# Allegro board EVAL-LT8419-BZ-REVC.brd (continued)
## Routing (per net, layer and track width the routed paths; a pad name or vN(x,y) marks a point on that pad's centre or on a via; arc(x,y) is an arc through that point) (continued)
V5: length 267.7
  TOP w0.254: 120.85,38.59 U7.9 ; R7.1 v1(105.4,27.28) ; R456.1 v1(109.57,27.28)
  TOP w0.305: C700.1 122.66,38.14 121.74,38.14 121.28,38.59 120.85,38.59
  TOP w0.381: C43.2 28.72,21.87 28.7,21.89 JP1.2
  L6_SIG w0.381: 123.83,32.7 123.83,35.67 122.55,36.95 v3(122.21,36.95) ; 123.83,32.7 131.95,24.59 203.63,24.59 205,25.96 JP3.1 214.19,25.96 v1(214.91,26.68) 215.82,27.59 224.16,27.59 224.22,27.53 v1(224.66,27.53) ; 123.83,32.7 122.8,32.7 117.16,27.06 111.18,27.06 110.96,27.28 v1(109.57,27.28) 108.83,28.02 106.13,28.02 v1(105.4,27.28) 102.65,30.04 102.65,39.29 103.26,39.91 103.26,40.35 v1(104.01,41.09) 105.07,40.02 106.09,40.02 106.76,40.69 106.76,44.53 108.49,46.26 108.49,47.27 107.45,48.31 107.45,48.42 v1(107.13,48.74) ; JP1.2 30.41,18.55 v1(32.51,18.55)
  L7_SIG w0.381: v1(32.51,18.55) 97.39,18.55 105.4,26.56 v1(105.4,27.28)
  BOTTOM w0.305: R6.2 v1(214.91,26.68)
  BOTTOM w0.381: R5.1 225.42,27.22 225.12,27.53 v1(224.66,27.53) ; R13.2 212.9,18.18 210.74,20.34 210.74,22.47 JP3.1
_N1: length 3.5
  TOP w0.203: C9.2 122.4,33.09 120.9,34.59 U7.1
_N2: length 8.3
  TOP w0.203: U7.4 121.02,36.09 122.21,34.9 v3(122.21,34.65) 122.4,34.46 C5.2
  L7_SIG w0.203: v3(126.4,33.78) 123.08,33.78 v3(122.21,34.65)
_N5: length 5.7
  TOP w0.203: U7.49 110.55,31.75 109.39,30.59 107.12,30.59 106.77,30.24 R17.1
_N7: length 8
  TOP w0.203: C11.2 v3(122.21,35.83) 121.84,35.83 121.06,36.62 121.06,36.83 120.8,37.09 U7.6
  L7_SIG w0.203: v3(126.4,35.15) 125.72,35.83 v3(122.21,35.83)
_N9: length 7.4
  TOP w0.203: C196.1 126.45,43.36 125.86,43.36 125.31,42.81 122.62,42.81 120.9,41.09 U7.14
_N20: length 8.8
  TOP w0.203: 126.4,39.81 R1.1 126.4,41.31 ; U7.13 120.94,40.59 122.78,42.43 125.21,42.43 125.63,42.01 C189.1
_N24: length 8.2
  TOP w0.203: R29.2 103.65,30.24 103.98,30.57 105.24,30.57 105.93,31.26 C39.1 106.63,32.23 108.55,34.15 U7.48
_N30: length 122.8
  TOP w0.203: U7.42 C2.1
  L6_SIG w0.203: E1.1 22.08,62.11 74.72,62.11 78.98,57.86 78.98,46.06 83.28,41.76 100.08,41.76 101.02,40.82 v3(101.02,37.68)
_N31: length 9.3
  TOP w0.203: U7.3 120.86,35.59 121.1,35.35 v3(121.1,35.09)
  L7_SIG w0.203: v3(121.1,35.09) 121.33,35.31 125.58,35.31 127.68,33.21 127.68,33.07 v3(127.86,32.89)
_N45: length 8
  TOP w0.203: U7.7 v3(121.1,37.59)
  L7_SIG w0.203: v3(121.1,37.59) v3(128.1,37.59)
_N68: length 3.3
  TOP w0.203: U7.44 107.32,36.59 106.2,35.47 R20.1
_N69: length 129.9
  TOP w0.203: v3(105.71,41.09) U7.35
  L6_SIG w0.203: v3(105.71,41.09) 102.92,43.88 83.32,43.88 80.06,47.14 80.06,58.33 75.06,63.33 22.85,63.33 20.13,66.04 20.13,71.68 E9.1
_N73: length 151.5
  TOP w0.203: U7.51 v3(111.55,31.54)
  L6_SIG w0.203: JP3.2 215.67,23.96 218.04,26.33 225.13,26.33 225.78,26.98 225.78,31.19 221.62,35.35 132.67,35.35 131.84,36.19 128.34,36.19 127.03,37.49 121.82,37.49 114.38,30.06 110.3,30.06 109.82,30.54 109.82,31.15 110.28,31.62 111.47,31.62 v3(111.55,31.54)
  BOTTOM w0.203: JP3.2 JP3.3
_N75: length 3.6
  TOP w0.203: U7.53 112.55,31.26 111.04,29.75 R44.2
_N76: length 120.4
  TOP w0.203: R456.2 109.57,30.23 109.98,30.65 v3(111.17,30.65) 111.35,30.65 112.05,31.35 U7.52
  L6_SIG w0.203: v3(111.17,30.65) 113.32,30.65 120.81,38.13 121.57,38.13 121.72,37.98 122.44,37.98 122.68,38.22 128.45,38.22 129.96,36.71 219.21,36.71 E21.1
_N78: length 26.4
  TOP w0.203: U7.50 111.05,31.28 v3(111.17,31.16)
  L7_SIG w0.203: v3(111.17,31.16) 110.94,31.16 108.87,29.09 108.87,24.88 115.91,17.84 117.46,17.84 119.99,15.32 E3.1
_N79: length 5.1
  TOP w0.203: R15.2 R9.2 122.92,43.62 122.46,43.16 122.37,43.16 120.8,41.59 U7.15
_N81: length 132.4
  TOP w0.203: C12.1 122.58,39.45 122.35,39.45 122.08,39.18 v3(122.08,38.85) 121.65,38.85 121.4,39.09 U7.10
  L6_SIG w0.203: E2.1 221.87,81.33 202.7,62.17 145.13,62.17 137.8,54.84 131.7,54.84 122.08,45.22 v3(122.08,38.85)
_N86: length 225.7
  TOP w0.203: v3(122.97,41.97) C148.1 122.4,41.21 120.78,39.59 U7.11
  L6_SIG w0.203: S1.2 221.59,21.08 224.14,21.08 226.65,23.59 226.65,45.81 223,49.47 193.6,49.47 189.87,53.2 182.89,53.2 179.8,50.12 179.8,46.74 177.92,44.85 126.95,44.85 124.08,41.97 v3(122.97,41.97)
  L7_SIG w0.203: S1.2 219.16,23.5 219.16,48.01 224.36,53.21 224.36,94.08 E5.1
_N95: length 4.9
  BOTTOM w0.203: C197.1 R468.1 R464.2 P28.1
_N100: length 6.1
  BOTTOM w0.203: J6.4 4.44,20.67 4.44,18.48 5.56,17.37 R415.1
_N101: length 7.8
  BOTTOM w0.203: R416.1 3.99,22.21 J6.6
_N102: length 9.6
  BOTTOM w0.203: J6.7 8.83,24.86 8.83,17.01 R12.1
_N108: length 12.9
  L5_GND w0.203: J6.11 14.92,29.96 v2(16.26,31.3)
  BOTTOM w0.203: J6.11 9.25,29.96 9.95,30.66 R439.2 ; U8.6 v2(16.26,31.3)
_N109: length 15.5
  L5_GND w0.171: 7.92,28.96 7.55,28.96
  L5_GND w0.203: v1(12.69,27.96) 11.69,28.96 7.92,28.96 ; J6.10 6.73,28.96 7.55,28.96
  BOTTOM w0.203: R440.1 12.69,32.29 12.93,32.54 C169.1 U8.8 ; R440.1 R441.1 v1(12.69,27.96) ; R440.1 R439.1
_N111: length 13.7
  L5_GND w0.203: J6.9 11.26,27.96 11.91,27.31 13.74,27.31 v1(14.39,27.96)
  BOTTOM w0.203: v1(14.39,27.96) R441.2 15.91,29.16 16.91,30.16 U8.5
_N113: length 9.9
  BOTTOM w0.203: U8.7 15.61,31.24 15.13,30.76 R440.2 14.39,30.66 13.5,29.76 JP21.1
_N115: length 1.8
  TOP w0.203: U1.A4 35.68,83.41 34.87,84.21 R702.2
_N120: length 1.9
  TOP w0.203: U1.B4 36.08,83.83 35.48,84.44 C4.2
_N122: length 2.1
  TOP w0.203: U1.C4 36.48,83.71 37.15,84.38 37.15,84.56 R705.1
_N123: length 1
  TOP w0.203: U1.D3 37.57,82.74 C701.1
_N125: length 1
  TOP w0.203: R4.1 36.08,81.23 U1.B1
_N126: length 0.9
  TOP w0.203: R3.1 37.51,82.34 U1.D2
_N129: length 105.9
  TOP w0.203: v3(41.04,79.51) 41.01,79.89 40.82,80.08 37.65,80.08 v3(36.65,81.08) 36.48,81.26 U1.C1 ; U1.D4 36.88,83.48 37.33,83.94 v3(37.77,83.94)
  L2_PWR w0.203: v3(39.7,79.52) 39.7,80.01 39.71,80.02 39.71,80.11
  L2_PWR w0.508: v3(39.71,81.86) v3(39.71,81.35) 39.71,80.11
  L5_GND w0.305: 41.05,79.51 v3(41.04,79.51) ; v3(41.04,79.51) 41.04,79.25 41.02,79.27 39.19,79.27 ; v3(41.04,79.51) v3(40.63,79.51) v3(40.23,79.51) v3(39.19,79.51) 39.19,79.27 ; v3(39.25,77.33) v3(39.63,77.33) v3(40.01,77.33) v3(40.39,77.33) v3(40.77,77.33) v3(41.15,77.33) v3(41.53,77.33) v3(41.91,77.33) v3(42.3,77.33) ; 33.31,74.53 v3(33.31,74.34) v3(32.93,74.34) v3(32.55,74.34) v3(32.16,74.34) v3(31.78,74.34) v3(31.4,74.34) v3(31.02,74.34) v3(30.64,74.34) v3(30.26,74.34) 30.26,74.53 ; 33.31,74.53 30.26,74.53 ; 33.31,74.53 v3(33.31,74.72) v3(32.93,74.72) v3(32.55,74.72) v3(32.16,74.72) v3(31.78,74.72) v3(31.4,74.72) v3(31.02,74.72) v3(30.64,74.72) v3(30.26,74.72) 30.26,74.53 ; 39.19,79.27 v3(39.19,79) 39.19,79.03 39.62,79.03 v3(39.69,79) v3(40.23,79) v3(40.63,79) v3(41.04,79) 41.05,79.01 ; v3(39.25,75.63) v3(39.63,75.63) v3(40.01,75.63) v3(40.39,75.63) v3(40.77,75.63) v3(41.15,75.63) v3(41.53,75.63) v3(41.91,75.63) v3(42.3,75.63) ; v3(30.26,78.18) v3(30.64,78.18) v3(31.02,78.18) v3(31.4,78.18) v3(31.78,78.18) v3(32.16,78.18) v3(32.55,78.18) v3(32.93,78.18) v3(33.31,78.18) ; v3(30.26,76.48) v3(30.64,76.48) v3(31.02,76.48) v3(31.4,76.48) v3(31.78,76.48) v3(32.16,76.48) v3(32.55,76.48) v3(32.93,76.48) v3(33.31,76.48)
  L6_SIG w0.305: v3(42.3,77.33) v3(41.91,77.33) v3(41.53,77.33) v3(41.15,77.33) v3(40.77,77.33) v3(40.39,77.33) v3(40.01,77.33) v3(39.63,77.33) v3(39.25,77.33) ; 30.26,74.53 v3(30.26,74.72) v3(30.64,74.72) v3(31.02,74.72) v3(31.4,74.72) v3(31.78,74.72) v3(32.16,74.72) v3(32.55,74.72) v3(32.93,74.72) v3(33.31,74.72) 33.31,74.53 ; 30.26,74.53 33.31,74.53 ; 30.26,74.53 v3(30.26,74.34) v3(30.64,74.34) v3(31.02,74.34) v3(31.4,74.34) v3(31.78,74.34) v3(32.16,74.34) v3(32.55,74.34) v3(32.93,74.34) v3(33.31,74.34) 33.31,74.53 ; v3(33.31,76.48) v3(32.93,76.48) v3(32.55,76.48) v3(32.16,76.48) v3(31.78,76.48) v3(31.4,76.48) v3(31.02,76.48) v3(30.64,76.48) v3(30.26,76.48) ; 41.01,79.27 39.19,79.27 ; 39.19,79.27 v3(39.19,79.51) v3(40.23,79.51) v3(40.63,79.51) v3(41.04,79.51) ; 39.19,79.27 v3(39.19,79) v3(39.69,79) v3(40.23,79) v3(40.63,79) v3(41.04,79) ; v3(30.26,78.18) v3(30.64,78.18) v3(31.02,78.18) v3(31.4,78.18) v3(31.78,78.18) v3(32.16,78.18) v3(32.55,78.18) v3(32.93,78.18) v3(33.31,78.18) ; v3(42.3,75.63) v3(41.91,75.63) v3(41.53,75.63) v3(41.15,75.63) v3(40.77,75.63) v3(40.39,75.63) v3(40.01,75.63) v3(39.63,75.63) v3(39.25,75.63)
  L7_SIG w0.305: v3(30.26,76.48) v3(30.64,76.48) v3(31.02,76.48) v3(31.4,76.48) v3(31.78,76.48) v3(32.16,76.48) v3(32.55,76.48) v3(32.93,76.48) v3(33.31,76.48) ; v3(39.25,75.63) v3(39.63,75.63) v3(40.01,75.63) v3(40.39,75.63) v3(40.77,75.63) v3(41.15,75.63) v3(41.53,75.63) v3(41.91,75.63) v3(42.3,75.63) ; 39.19,79.26 39.2,79.27 41.01,79.27 ; 39.19,79.26 v3(39.19,79) v3(39.69,79) v3(40.23,79) v3(40.63,79) v3(41.04,79) v3(41.04,79.51) v3(40.63,79.51) v3(40.23,79.51) v3(39.19,79.51) 39.19,79.26 ; 33.31,74.53 v3(33.31,74.34) v3(32.93,74.34) v3(32.55,74.34) v3(32.16,74.34) v3(31.78,74.34) v3(31.4,74.34) v3(31.02,74.34) v3(30.64,74.34) v3(30.26,74.34) 30.26,74.53 ; 33.31,74.53 v3(33.31,74.72) v3(32.93,74.72) v3(32.55,74.72) v3(32.16,74.72) v3(31.78,74.72) v3(31.4,74.72) v3(31.02,74.72) v3(30.64,74.72) v3(30.26,74.72) 30.26,74.53 ; 33.31,74.53 30.26,74.53 ; v3(33.31,78.18) v3(32.93,78.18) v3(32.55,78.18) v3(32.16,78.18) v3(31.78,78.18) v3(31.4,78.18) v3(31.02,78.18) v3(30.64,78.18) v3(30.26,78.18) ; v3(42.3,77.33) v3(41.91,77.33) v3(41.53,77.33) v3(41.15,77.33) v3(40.77,77.33) v3(40.39,77.33) v3(40.01,77.33) v3(39.63,77.33) v3(39.25,77.33) ; v2(36.28,67.56) 36.28,67.15
  BOTTOM w0.254: v2(36.28,67.56) 36.28,66.55 35.58,65.85 28.47,65.85 28.47,65.87 28.26,66.08 R706.1
  vias: v2(29.72,69.09) v2(29.72,67.82) v2(29.72,66.55) v2(29.72,65.28) v2(30.99,65.28) v2(31.07,66.5) v2(31.2,69.81) v2(31.2,68.68) v2(31.2,67.56) v2(32.34,66.5) v2(32.26,65.28) v2(32.47,69.81) v2(32.47,68.68) v2(32.47,67.56) v2(33.53,65.28) v2(33.61,66.5) v2(33.74,69.81) v2(33.74,68.68) v2(33.74,67.56) v2(34.8,65.28) v2(34.88,66.5) v2(35.01,69.81) v2(35.01,68.68) v2(35.01,67.56) v2(36.07,65.28) v2(36.28,69.81) v2(36.28,68.68) v2(37.49,66.47) v2(37.55,69.81) v2(37.55,68.68) v2(37.55,67.56) v2(37.58,65.33) v2(38.82,69.81) v2(38.82,68.68) v2(38.82,67.56) v2(38.76,66.47) v2(38.85,65.33) v2(39.79,66.42) v2(39.88,65.28) v2(40.09,69.81) v2(40.09,68.68) v2(40.09,67.56) v2(41.06,66.42) v2(41.15,65.28) v2(41.36,69.81) v2(41.36,68.68) v2(41.36,67.56) v2(42.33,66.42) v2(42.4,69.09) v2(42.4,67.82) v2(42.42,65.28) v2(43.6,66.42) v2(43.69,69.09) v2(43.69,67.82) v2(43.69,65.28) v2(44.87,66.42) v2(44.96,69.09) v2(44.96,67.82) v2(44.96,65.28) v2(46.14,66.42) v2(46.23,69.09) v2(46.23,67.82) v2(46.23,65.28) v2(47.41,66.42) v2(47.5,69.09) v2(47.5,67.82) v2(47.5,65.28) v2(48.68,66.42) v2(48.77,69.09) v2(48.77,67.82) v2(48.77,65.28)
_N137: length 97.5
  L7_SIG w0.305: v2(36.28,56.26) 36.28,55.86 36.95,55.19 46.63,55.19 49.33,52.49 49.33,48.74 54.77,43.3 107.11,43.3 108.34,42.07 113.35,42.07 118.86,47.58 118.86,49.26 119.57,49.98 v3(119.57,51.58)
  vias: v2(31.2,61.2) v2(31.2,60.07) v2(31.2,58.95) v2(32.47,61.2) v2(32.47,60.07) v2(32.47,58.95) v2(33.74,61.2) v2(33.74,60.07) v2(33.74,58.95) v2(35.01,61.2) v2(35.01,60.07) v2(35.01,58.95) v2(36.28,61.2) v2(36.28,60.07) v2(36.28,58.95) v2(37.55,61.2) v2(37.55,60.07) v2(37.55,58.95) v2(38.82,61.2) v2(38.82,60.07) v2(38.82,58.95) v2(40.09,61.2) v2(40.09,60.07) v2(40.09,58.95) v2(41.36,61.2) v2(41.36,60.07) v2(41.36,58.95)
_N157: length 1.8
  TOP w0.203: R711.2 63.82,84.21 64.63,83.41 U2.A4
_N158: length 1.9
  TOP w0.203: U2.B4 65.03,83.83 64.43,84.44 C716.2
_N159: length 2.1
  TOP w0.203: U2.C4 65.43,83.71 66.1,84.38 66.1,84.56 R714.1
_N160: length 1
  TOP w0.203: C719.1 66.52,82.74 U2.D3
_N161: length 1
  TOP w0.203: U2.B1 65.03,81.23 R716.1
_N162: length 0.9
  TOP w0.203: U2.D2 66.46,82.34 R715.1
_N163: length 104.3
  TOP w0.203: U2.C1 65.43,81.26 v3(65.6,81.08) 66.6,80.08 69.68,80.08 69.84,79.92 69.84,79.46 ; U2.D4 65.83,83.48 66.29,83.94 v3(66.72,83.94)
  L2_PWR w0.203: 68.66,80.01 v3(68.66,79.54)
  L2_PWR w0.508: v3(68.66,81.86) v3(68.66,81.35) 68.66,80.01
  L5_GND w0.305: v3(71.25,77.33) v3(70.87,77.33) v3(70.48,77.33) v3(70.1,77.33) v3(69.72,77.33) v3(69.34,77.33) v3(68.96,77.33) v3(68.58,77.33) v3(68.2,77.33) ; v3(62.26,76.48) v3(61.88,76.48) v3(61.5,76.48) v3(61.12,76.48) v3(60.73,76.48) v3(60.35,76.48) v3(59.97,76.48) v3(59.59,76.48) v3(59.21,76.48) ; v3(69.59,79.03) v3(70,79.03) ; 59.21,74.53 v3(59.21,74.72) v3(59.59,74.72) v3(59.97,74.72) v3(60.35,74.72) v3(60.73,74.72) v3(61.12,74.72) v3(61.5,74.72) v3(61.88,74.72) v3(62.26,74.72) 62.26,74.53 ; 59.21,74.53 62.26,74.53 ; 59.21,74.53 v3(59.21,74.34) v3(59.59,74.34) v3(59.97,74.34) v3(60.35,74.34) v3(60.73,74.34) v3(61.12,74.34) v3(61.5,74.34) v3(61.88,74.34) v3(62.26,74.34) 62.26,74.53 ; 69.97,79.3 68.14,79.3 v3(68.14,79.03) 68.14,79.06 68.57,79.06 v3(68.65,79.03) v3(69.18,79.03) ; v3(70,79.54) v3(69.59,79.54) v3(69.18,79.54) v3(68.14,79.54) ; v3(59.21,78.18) v3(59.59,78.18) v3(59.97,78.18) v3(60.35,78.18) v3(60.73,78.18) v3(61.12,78.18) v3(61.5,78.18) v3(61.88,78.18) v3(62.26,78.18) ; v3(68.2,75.63) v3(68.58,75.63) v3(68.96,75.63) v3(69.34,75.63) v3(69.72,75.63) v3(70.1,75.63) v3(70.48,75.63) v3(70.87,75.63) v3(71.25,75.63)
  L6_SIG w0.305: v3(62.26,78.18) v3(61.88,78.18) v3(61.5,78.18) v3(61.12,78.18) v3(60.73,78.18) v3(60.35,78.18) v3(59.97,78.18) v3(59.59,78.18) v3(59.21,78.18) ; v3(62.26,76.48) v3(61.88,76.48) v3(61.5,76.48) v3(61.12,76.48) v3(60.73,76.48) v3(60.35,76.48) v3(59.97,76.48) v3(59.59,76.48) v3(59.21,76.48) ; v3(70,79.54) v3(69.59,79.54) v3(69.18,79.54) v3(68.14,79.54) 68.14,79.3 69.97,79.3 ; v3(68.2,77.33) v3(68.58,77.33) v3(68.96,77.33) v3(69.34,77.33) v3(69.72,77.33) v3(70.1,77.33) v3(70.48,77.33) v3(70.87,77.33) v3(71.25,77.33) ; v3(70,79.03) v3(69.59,79.03) v3(69.18,79.03) v3(68.65,79.03) v3(68.14,79.03) ; 59.21,74.53 v3(59.21,74.34) v3(59.59,74.34) v3(59.97,74.34) v3(60.35,74.34) v3(60.73,74.34) v3(61.12,74.34) v3(61.5,74.34) v3(61.88,74.34) v3(62.26,74.34) 62.26,74.53 ; 59.21,74.53 62.26,74.53 ; 59.21,74.53 v3(59.21,74.72) v3(59.59,74.72) v3(59.97,74.72) v3(60.35,74.72) v3(60.73,74.72) v3(61.12,74.72) v3(61.5,74.72) v3(61.88,74.72) v3(62.26,74.72) 62.26,74.53 ; v3(68.2,75.63) v3(68.58,75.63) v3(68.96,75.63) v3(69.34,75.63) v3(69.72,75.63) v3(70.1,75.63) v3(70.48,75.63) v3(70.87,75.63) v3(71.25,75.63)
  L7_SIG w0.305: v3(59.21,78.18) v3(59.59,78.18) v3(59.97,78.18) v3(60.35,78.18) v3(60.73,78.18) v3(61.12,78.18) v3(61.5,78.18) v3(61.88,78.18) v3(62.26,78.18) ; v3(59.21,76.48) v3(59.59,76.48) v3(59.97,76.48) v3(60.35,76.48) v3(60.73,76.48) v3(61.12,76.48) v3(61.5,76.48) v3(61.88,76.48) v3(62.26,76.48) ; 68.14,79.29 v3(68.14,79.03) v3(68.65,79.03) v3(69.18,79.03) v3(69.59,79.03) v3(70,79.03) v3(70,79.54) v3(69.59,79.54) v3(69.18,79.54) 69.18,79.54 v3(68.66,79.54) 68.65,79.54 v3(68.14,79.54) 68.14,79.29 ; 68.14,79.29 68.15,79.3 69.97,79.3 ; v3(71.25,77.33) v3(70.87,77.33) v3(70.48,77.33) v3(70.1,77.33) v3(69.72,77.33) v3(69.34,77.33) v3(68.96,77.33) v3(68.58,77.33) v3(68.2,77.33) ; v3(71.25,75.63) v3(70.87,75.63) v3(70.48,75.63) v3(70.1,75.63) v3(69.72,75.63) v3(69.34,75.63) v3(68.96,75.63) v3(68.58,75.63) v3(68.2,75.63) ; 59.21,74.53 v3(59.21,74.72) v3(59.59,74.72) v3(59.97,74.72) v3(60.35,74.72) v3(60.73,74.72) v3(61.12,74.72) v3(61.5,74.72) v3(61.88,74.72) v3(62.26,74.72) 62.26,74.53 ; 59.21,74.53 62.26,74.53 ; 59.21,74.53 v3(59.21,74.34) v3(59.59,74.34) v3(59.97,74.34) v3(60.35,74.34) v3(60.73,74.34) v3(61.12,74.34) v3(61.5,74.34) v3(61.88,74.34) v3(62.26,74.34) 62.26,74.53
  BOTTOM w0.254: R717.1 57,66.16 57.2,65.95 64.62,65.95 65.23,66.56 v2(65.23,67.56)
  vias: v2(58.93,69.09) v2(58.93,67.82) v2(58.93,66.55) v2(58.93,65.28) v2(60.15,69.81) v2(60.15,68.68) v2(60.15,67.56) v2(60.2,66.55) v2(60.2,65.28) v2(61.42,69.81) v2(61.42,68.68) v2(61.42,67.56) v2(61.47,66.55) v2(61.47,65.28) v2(62.69,69.81) v2(62.69,68.68) v2(62.69,67.56) v2(62.74,66.55) v2(62.74,65.28) v2(63.96,69.81) v2(63.96,68.68) v2(63.96,67.56) v2(64.01,66.55) v2(64.01,65.28) v2(65.23,69.81) v2(65.23,68.68) v2(65.28,65.28) v2(66.5,69.81) v2(66.5,68.68) v2(66.5,67.56) v2(66.51,66.5) v2(66.55,65.25) v2(67.77,69.81) v2(67.77,68.68) v2(67.77,67.56) v2(67.82,66.55) v2(67.82,65.25) v2(69.04,69.81) v2(69.04,68.68) v2(69.04,67.56) v2(69.09,66.55) v2(69.09,65.28) v2(70.31,69.81) v2(70.31,68.68) v2(70.31,67.56) v2(70.36,66.55) v2(70.36,65.28) v2(71.63,69.09) v2(71.63,67.82) v2(71.63,66.55) v2(71.63,65.28) v2(72.9,69.09) v2(72.9,67.82) v2(72.9,66.55) v2(72.9,65.28) v2(74.17,66.55) v2(74.17,65.28)
_N164: length 60
  L7_SIG w0.305: v3(118.07,51.58) 118.07,50.5 114.58,47 108.4,47 107.75,46.35 98.25,46.35 89.43,55.17 65.92,55.17 65.23,55.86 v2(65.23,56.26)
  vias: v2(60.15,61.2) v2(60.15,60.07) v2(60.15,58.95) v2(61.42,61.2) v2(61.42,60.07) v2(61.42,58.95) v2(62.69,61.2) v2(62.69,60.07) v2(62.69,58.95) v2(63.96,61.2) v2(63.96,60.07) v2(63.96,58.95) v2(65.23,61.2) v2(65.23,60.07) v2(65.23,58.95) v2(66.5,61.2) v2(66.5,60.07) v2(66.5,58.95) v2(67.77,61.2) v2(67.77,60.07) v2(67.77,58.95) v2(69.04,61.2) v2(69.04,60.07) v2(69.04,58.95) v2(70.31,61.2) v2(70.31,60.07) v2(70.31,58.95)
_N189: length 1.8
  TOP w0.203: U3.A4 100.19,83.41 99.39,84.21 R722.2
_N190: length 1.9
  TOP w0.203: C750.2 99.99,84.44 100.59,83.83 U3.B4
_N191: length 2.1
  TOP w0.203: U3.C4 100.99,83.71 101.67,84.38 101.67,84.56 R725.1
_N192: length 1
  TOP w0.203: U3.D3 102.09,82.74 C753.1
_N193: length 1
  TOP w0.203: U3.B1 100.59,81.23 R727.1
_N194: length 0.9
  TOP w0.203: R726.1 102.03,82.34 U3.D2
_N195: length 107.2
  TOP w0.203: U3.C1 100.99,81.26 v3(101.17,81.08) 102.17,80.08 105.24,80.08 105.4,79.92 105.4,79.46 ; U3.D4 101.39,83.48 101.85,83.94 v3(102.28,83.94)
  L2_PWR w0.203: 104.22,80.01 104.24,79.99 v3(104.24,79.54)
  L2_PWR w0.508: v3(104.22,81.86) v3(104.22,81.35) 104.22,80.01
  L5_GND w0.305: 103.73,79.3 v3(103.73,79.03) 103.73,79.06 104.16,79.06 v3(104.24,79.03) v3(104.77,79.03) v3(105.18,79.03) v3(105.58,79.03) ; 103.73,79.3 105.56,79.3 ; 103.73,79.3 v3(103.73,79.54) v3(104.77,79.54) v3(105.18,79.54) v3(105.58,79.54) ; v3(94.78,78.18) v3(95.16,78.18) v3(95.54,78.18) v3(95.92,78.18) v3(96.3,78.18) v3(96.68,78.18) v3(97.06,78.18) v3(97.44,78.18) v3(97.82,78.18) ; 94.78,74.53 v3(94.78,74.34) v3(95.16,74.34) v3(95.54,74.34) v3(95.92,74.34) v3(96.3,74.34) v3(96.68,74.34) v3(97.06,74.34) v3(97.44,74.34) v3(97.82,74.34) 97.82,74.53 ; 94.78,74.53 v3(94.78,74.72) v3(95.16,74.72) v3(95.54,74.72) v3(95.92,74.72) v3(96.3,74.72) v3(96.68,74.72) v3(97.06,74.72) v3(97.44,74.72) v3(97.82,74.72) 97.82,74.53 ; 94.78,74.53 97.82,74.53 ; v3(103.76,77.33) v3(104.14,77.33) v3(104.53,77.33) v3(104.91,77.33) v3(105.29,77.33) v3(105.67,77.33) v3(106.05,77.33) v3(106.43,77.33) v3(106.81,77.33) ; v3(106.81,75.63) v3(106.43,75.63) v3(106.05,75.63) v3(105.67,75.63) v3(105.29,75.63) v3(104.91,75.63) v3(104.53,75.63) v3(104.14,75.63) v3(103.76,75.63) ; v3(97.82,76.48) v3(97.44,76.48) v3(97.06,76.48) v3(96.68,76.48) v3(96.3,76.48) v3(95.92,76.48) v3(95.54,76.48) v3(95.16,76.48) v3(94.78,76.48)
  L6_SIG w0.305: v3(105.58,79.03) v3(105.18,79.03) v3(104.77,79.03) v3(104.24,79.03) v3(103.73,79.03) 103.73,79.3 ; 94.78,74.53 v3(94.78,74.34) v3(95.16,74.34) v3(95.54,74.34) v3(95.92,74.34) v3(96.3,74.34) v3(96.68,74.34) v3(97.06,74.34) v3(97.44,74.34) v3(97.82,74.34) 97.82,74.53 ; 94.78,74.53 97.82,74.53 ; 94.78,74.53 v3(94.78,74.72) v3(95.16,74.72) v3(95.54,74.72) v3(95.92,74.72) v3(96.3,74.72) v3(96.68,74.72) v3(97.06,74.72) v3(97.44,74.72) v3(97.82,74.72) 97.82,74.53 ; v3(103.76,75.63) v3(104.14,75.63) v3(104.53,75.63) v3(104.91,75.63) v3(105.29,75.63) v3(105.67,75.63) v3(106.05,75.63) v3(106.43,75.63) v3(106.81,75.63) ; 103.73,79.3 v3(103.73,79.54) v3(104.77,79.54) v3(105.18,79.54) v3(105.58,79.54) ; 103.73,79.3 105.56,79.3 ; v3(106.81,77.33) v3(106.43,77.33) v3(106.05,77.33) v3(105.67,77.33) v3(105.29,77.33) v3(104.91,77.33) v3(104.53,77.33) v3(104.14,77.33) v3(103.76,77.33) ; v3(94.78,78.18) v3(95.16,78.18) v3(95.54,78.18) v3(95.92,78.18) v3(96.3,78.18) v3(96.68,78.18) v3(97.06,78.18) v3(97.44,78.18) v3(97.82,78.18) ; v3(97.82,76.48) v3(97.44,76.48) v3(97.06,76.48) v3(96.68,76.48) v3(96.3,76.48) v3(95.92,76.48) v3(95.54,76.48) v3(95.16,76.48) v3(94.78,76.48)
  L7_SIG w0.305: 94.78,74.53 v3(94.78,74.34) v3(95.16,74.34) v3(95.54,74.34) v3(95.92,74.34) v3(96.3,74.34) v3(96.68,74.34) v3(97.06,74.34) v3(97.44,74.34) v3(97.82,74.34) 97.82,74.53 ; 94.78,74.53 v3(94.78,74.72) v3(95.16,74.72) v3(95.54,74.72) v3(95.92,74.72) v3(96.3,74.72) v3(96.68,74.72) v3(97.06,74.72) v3(97.44,74.72) v3(97.82,74.72) 97.82,74.53 ; 94.78,74.53 97.82,74.53 ; v3(94.78,78.18) v3(95.16,78.18) v3(95.54,78.18) v3(95.92,78.18) v3(96.3,78.18) v3(96.68,78.18) v3(97.06,78.18) v3(97.44,78.18) v3(97.82,78.18) ; v3(94.78,76.48) v3(95.16,76.48) v3(95.54,76.48) v3(95.92,76.48) v3(96.3,76.48) v3(96.68,76.48) v3(97.06,76.48) v3(97.44,76.48) v3(97.82,76.48) ; v3(103.76,75.63) v3(104.14,75.63) v3(104.53,75.63) v3(104.91,75.63) v3(105.29,75.63) v3(105.67,75.63) v3(106.05,75.63) v3(106.43,75.63) v3(106.81,75.63) ; 105.56,79.3 103.74,79.3 103.73,79.29 ; 103.73,79.29 v3(103.73,79.54) v3(104.77,79.54) v3(105.18,79.54) v3(105.58,79.54) v3(105.58,79.03) v3(105.18,79.03) v3(104.77,79.03) v3(104.24,79.03) v3(103.73,79.03) 103.73,79.29 ; v3(103.76,77.33) v3(104.14,77.33) v3(104.53,77.33) v3(104.91,77.33) v3(105.29,77.33) v3(105.67,77.33) v3(106.05,77.33) v3(106.43,77.33) v3(106.81,77.33)
  BOTTOM w0.254: v2(98.75,67.56) 98.75,66.85 98.38,66.48 88.69,66.48 88.38,66.18 R728.1
  vias: v2(90.68,65.28) v2(90.68,64.01) v2(90.68,62.74) v2(91.95,65.28) v2(91.95,64.01) v2(91.95,62.74) v2(93.22,65.28) v2(93.22,64.01) v2(93.22,62.74) v2(93.67,69.81) v2(93.67,68.68) v2(93.67,67.56) v2(94.49,65.28) v2(94.49,64.01) v2(94.49,62.74) v2(94.94,69.81) v2(94.94,68.68) v2(94.94,67.56) v2(95.76,65.28) v2(95.76,64.01) v2(95.76,62.74) v2(96.21,69.81) v2(96.21,68.68) v2(96.21,67.56) v2(97.03,65.28) v2(97.03,64.01) v2(97.03,62.74) v2(97.48,69.81) v2(97.48,68.68) v2(97.48,67.56) v2(98.3,65.28) v2(98.3,64.01) v2(98.3,62.74) v2(98.75,69.81) v2(98.75,68.68) v2(99.59,65.28) v2(99.57,64.01) v2(99.57,62.74) v2(100.02,69.81) v2(100.02,68.68) v2(100.02,67.56) v2(100.84,62.74) v2(100.86,65.28) v2(100.86,64.01) v2(101.29,69.81) v2(101.29,68.68) v2(101.29,67.56) v2(102.11,65.28) v2(102.13,64.01) v2(102.11,62.74) v2(102.56,69.81) v2(102.56,68.68) v2(102.56,67.56) v2(103.38,65.28) v2(103.4,64.01) v2(103.38,62.74) v2(103.83,69.81) v2(103.83,68.68) v2(103.83,67.56) v2(104.65,65.28) v2(104.67,64.01) v2(104.65,62.74) v2(105.92,65.28) v2(105.94,64.01) v2(105.92,62.74)
_N196: length 16
  L7_SIG w0.305: v2(96.44,56.26) 96.44,55.86 97.14,55.16 106.75,55.16 109.97,51.94 109.97,51.8 v3(110.19,51.58)
  vias: v2(93.67,61.2) v2(93.67,60.07) v2(93.67,58.95) v2(94.94,61.2) v2(94.94,60.07) v2(94.94,58.95) v2(96.21,61.2) v2(96.21,60.07) v2(96.21,58.95) v2(97.48,61.2) v2(97.48,60.07) v2(97.48,58.95) v2(98.75,61.2) v2(98.75,60.07) v2(98.75,58.95) v2(100.02,61.2) v2(100.02,60.07) v2(100.02,58.95) v2(101.29,61.2) v2(101.29,60.07) v2(101.29,58.95) v2(102.56,61.2) v2(102.56,60.07) v2(102.56,58.95) v2(103.83,61.2) v2(103.83,60.07) v2(103.83,58.95)
_N205: length 1.8
  TOP w0.203: U4.A4 129.14,83.41 128.34,84.21 R801.2
_N206: length 1.9
  TOP w0.203: U4.B4 129.54,83.83 128.94,84.44 C800.2
_N207: length 2.1
  TOP w0.203: R804.1 130.62,84.56 130.62,84.38 129.94,83.71 U4.C4
_N208: length 1
  TOP w0.203: U4.D3 131.04,82.74 C803.1
_N209: length 1
  TOP w0.203: U4.B1 129.54,81.23 R806.1
_N210: length 0.9
  TOP w0.203: U4.D2 130.98,82.34 R805.1
_N211: length 106
  TOP w0.203: U4.C1 129.94,81.26 v3(130.12,81.08) 131.12,80.08 134.19,80.08 134.35,79.92 134.35,79.46 ; U4.D4 130.34,83.48 130.8,83.94 v3(131.23,83.94)
  L2_PWR w0.203: 133.17,80.14 v3(133.17,79.54)
  L2_PWR w0.508: v3(133.17,81.86) v3(133.17,81.35) 133.17,81.35 133.17,80.14
  L5_GND w0.305: v3(134.51,79.54) v3(134.11,79.54) v3(133.7,79.54) v3(132.66,79.54) 132.66,79.3 ; v3(135.76,75.63) v3(135.38,75.63) v3(135,75.63) v3(134.62,75.63) v3(134.24,75.63) v3(133.86,75.63) v3(133.48,75.63) v3(133.1,75.63) v3(132.71,75.63) ; 123.73,74.53 v3(123.73,74.34) v3(124.11,74.34) v3(124.49,74.34) v3(124.87,74.34) v3(125.25,74.34) v3(125.63,74.34) v3(126.01,74.34) v3(126.39,74.34) v3(126.77,74.34) 126.77,74.53 ; 123.73,74.53 v3(123.73,74.72) v3(124.11,74.72) v3(124.49,74.72) v3(124.87,74.72) v3(125.25,74.72) v3(125.63,74.72) v3(126.01,74.72) v3(126.39,74.72) v3(126.77,74.72) 126.77,74.53 ; 123.73,74.53 126.77,74.53 ; v3(132.71,77.33) v3(133.1,77.33) v3(133.48,77.33) v3(133.86,77.33) v3(134.24,77.33) v3(134.62,77.33) v3(135,77.33) v3(135.38,77.33) v3(135.76,77.33) ; v3(126.77,76.48) v3(126.39,76.48) v3(126.01,76.48) v3(125.63,76.48) v3(125.25,76.48) v3(124.87,76.48) v3(124.49,76.48) v3(124.11,76.48) v3(123.73,76.48) ; v3(134.51,79.03) v3(134.11,79.03) v3(133.7,79.03) v3(133.17,79.03) 133.09,79.06 132.66,79.06 v3(132.66,79.03) 132.66,79.3 ; v3(126.77,78.18) v3(126.39,78.18) v3(126.01,78.18) v3(125.63,78.18) v3(125.25,78.18) v3(124.87,78.18) v3(124.49,78.18) v3(124.11,78.18) v3(123.73,78.18) ; 134.49,79.3 132.66,79.3
  L6_SIG w0.305: 123.73,74.53 v3(123.73,74.34) v3(124.11,74.34) v3(124.49,74.34) v3(124.87,74.34) v3(125.25,74.34) v3(125.63,74.34) v3(126.01,74.34) v3(126.39,74.34) v3(126.77,74.34) 126.77,74.53 ; 123.73,74.53 v3(123.73,74.72) v3(124.11,74.72) v3(124.49,74.72) v3(124.87,74.72) v3(125.25,74.72) v3(125.63,74.72) v3(126.01,74.72) v3(126.39,74.72) v3(126.77,74.72) 126.77,74.53 ; 123.73,74.53 126.77,74.53 ; v3(126.77,78.18) v3(126.39,78.18) v3(126.01,78.18) v3(125.63,78.18) v3(125.25,78.18) v3(124.87,78.18) v3(124.49,78.18) v3(124.11,78.18) v3(123.73,78.18) ; v3(134.51,79.03) v3(134.11,79.03) v3(133.7,79.03) v3(133.17,79.03) v3(132.66,79.03) 132.66,79.3 ; v3(132.71,77.33) v3(133.1,77.33) v3(133.48,77.33) v3(133.86,77.33) v3(134.24,77.33) v3(134.62,77.33) v3(135,77.33) v3(135.38,77.33) v3(135.76,77.33) ; v3(135.76,75.63) v3(135.38,75.63) v3(135,75.63) v3(134.62,75.63) v3(134.24,75.63) v3(133.86,75.63) v3(133.48,75.63) v3(133.1,75.63) v3(132.71,75.63) ; 132.66,79.3 v3(132.66,79.54) v3(133.7,79.54) v3(134.11,79.54) v3(134.51,79.54) ; 132.66,79.3 134.49,79.3 ; v3(126.77,76.48) v3(126.39,76.48) v3(126.01,76.48) v3(125.63,76.48) v3(125.25,76.48) v3(124.87,76.48) v3(124.49,76.48) v3(124.11,76.48) v3(123.73,76.48)
  L7_SIG w0.305: v3(126.77,76.48) v3(126.39,76.48) v3(126.01,76.48) v3(125.63,76.48) v3(125.25,76.48) v3(124.87,76.48) v3(124.49,76.48) v3(124.11,76.48) v3(123.73,76.48) ; 132.66,79.29 v3(132.66,79.54) v3(133.7,79.54) v3(134.11,79.54) v3(134.51,79.54) v3(134.51,79.03) v3(134.11,79.03) v3(133.7,79.03) v3(133.17,79.03) v3(132.66,79.03) 132.66,79.29 ; 132.66,79.29 132.67,79.3 134.49,79.3 ; v3(132.71,77.33) v3(133.1,77.33) v3(133.48,77.33) v3(133.86,77.33) v3(134.24,77.33) v3(134.62,77.33) v3(135,77.33) v3(135.38,77.33) v3(135.76,77.33) ; v3(132.71,75.63) v3(133.1,75.63) v3(133.48,75.63) v3(133.86,75.63) v3(134.24,75.63) v3(134.62,75.63) v3(135,75.63) v3(135.38,75.63) v3(135.76,75.63) ; 126.77,74.53 v3(126.77,74.34) v3(126.39,74.34) v3(126.01,74.34) v3(125.63,74.34) v3(125.25,74.34) v3(124.87,74.34) v3(124.49,74.34) v3(124.11,74.34) v3(123.73,74.34) 123.73,74.53 ; 126.77,74.53 v3(126.77,74.72) v3(126.39,74.72) v3(126.01,74.72) v3(125.63,74.72) v3(125.25,74.72) v3(124.87,74.72) v3(124.49,74.72) v3(124.11,74.72) v3(123.73,74.72) 123.73,74.53 ; 126.77,74.53 123.73,74.53 ; v3(123.73,78.18) v3(124.11,78.18) v3(124.49,78.18) v3(124.87,78.18) v3(125.25,78.18) v3(125.63,78.18) v3(126.01,78.18) v3(126.39,78.18) v3(126.77,78.18)
  BOTTOM w0.254: R807.1 121.02,66.2 130.53,66.2 130.84,66.5 v2(130.84,67.38)
  BOTTOM w0.305: v2(130.84,68.5) L4.1
  vias: v2(124.97,65.28) v2(124.97,64.01) v2(124.97,62.74) v2(125.76,69.63) v2(125.76,68.5) v2(125.76,67.38) v2(126.24,65.28) v2(126.24,64.01) v2(126.24,62.74) v2(127.03,69.63) v2(127.03,68.5) v2(127.03,67.38) v2(127.51,65.28) v2(127.51,64.01) v2(127.51,62.74) v2(128.3,69.63) v2(128.3,68.5) v2(128.3,67.38) v2(128.78,65.28) v2(128.78,64.01) v2(128.78,62.74) v2(129.57,69.63) v2(129.57,68.5) v2(129.57,67.38) v2(130.05,65.28) v2(130.05,64.01) v2(130.05,62.74) v2(130.84,69.63) v2(131.25,65.3) v2(131.25,64.03) v2(131.25,62.76) v2(132.11,69.63) v2(132.11,68.5) v2(132.11,67.38) v2(132.59,65.28) v2(132.59,64.01) v2(132.59,62.74) v2(133.38,69.63) v2(133.38,68.5) v2(133.38,67.38) v2(133.85,65.26) v2(133.86,64.01) v2(133.86,62.74) v2(134.65,69.63) v2(134.65,68.5) v2(134.65,67.38) v2(135.12,65.26) v2(135.13,64.01) v2(135.13,62.74) v2(135.92,69.63) v2(135.92,68.5) v2(135.92,67.38) v2(136.39,65.26) v2(136.41,64.01) v2(136.4,62.74)
_N212: length 50.8
  L7_SIG w0.305: v2(134.1,56.26) 134.1,55.54 133.76,55.19 130.53,55.19 129.48,54.15 129.48,50.43 131.24,48.67 131.24,40.62 129.66,39.03 123.94,39.03 122.64,40.33 120.87,40.33 119.52,38.97 119.52,35.59 113.73,29.8 113.73,27.09 v3(111.74,25.1)
  vias: v2(125.76,60.68) v2(125.76,59.56) v2(125.76,58.43) v2(127.03,60.68) v2(127.03,59.56) v2(127.03,58.43) v2(128.3,60.68) v2(128.3,59.56) v2(128.3,58.43) v2(129.57,60.68) v2(129.57,59.56) v2(129.57,58.43) v2(130.78,60.67) v2(130.78,59.55) v2(130.78,58.42) v2(132.11,60.68) v2(132.11,59.56) v2(132.11,58.43) v2(133.38,60.68) v2(133.38,59.56) v2(133.38,58.43) v2(134.65,60.68) v2(134.65,59.56) v2(134.65,58.43) v2(135.92,60.68) v2(135.92,59.56) v2(135.92,58.43)
_N213: length 1.8
  TOP w0.203: R813.2 163.9,84.21 164.71,83.41 U5.A4
_N214: length 1.9
  TOP w0.203: U5.B4 165.11,83.83 164.51,84.44 C834.2
_N215: length 2.1
  TOP w0.203: R816.1 166.18,84.56 166.18,84.38 165.51,83.71 U5.C4
_N216: length 1
  TOP w0.203: C837.1 166.6,82.74 U5.D3
_N217: length 1
  TOP w0.203: U5.B1 165.11,81.23 R818.1
_N218: length 0.9
  TOP w0.203: R817.1 166.54,82.34 U5.D2
_N219: length 105.3
  TOP w0.203: U5.D4 165.91,83.48 166.37,83.94 v3(166.8,83.94) ; 169.92,79.46 169.92,79.92 169.76,80.08 166.68,80.08 v3(165.68,81.08) 165.51,81.26 U5.C1
  L2_PWR w0.203: 168.76,80.14 v3(168.76,79.57)
  L2_PWR w0.508: v3(168.74,81.86) v3(168.74,81.35) 168.76,81.33 168.76,80.14
  L5_GND w0.305: 170.07,79.32 168.24,79.32 ; 168.24,79.32 v3(168.24,79.56) v3(169.28,79.56) v3(169.69,79.56) v3(170.1,79.56) ; 168.24,79.32 v3(168.24,79.06) 168.24,79.08 168.68,79.08 168.68,79.08 v3(168.75,79.06) v3(169.28,79.06) v3(169.69,79.06) v3(170.1,79.06) ; v3(159.29,76.48) v3(159.67,76.48) v3(160.05,76.48) v3(160.43,76.48) v3(160.82,76.48) v3(161.2,76.48) v3(161.58,76.48) v3(161.96,76.48) v3(162.34,76.48) ; 159.29,74.53 v3(159.29,74.72) v3(159.67,74.72) v3(160.05,74.72) v3(160.43,74.72) v3(160.82,74.72) v3(161.2,74.72) v3(161.58,74.72) v3(161.96,74.72) v3(162.34,74.72) 162.34,74.53 ; 159.29,74.53 162.34,74.53 ; 159.29,74.53 v3(159.29,74.34) v3(159.67,74.34) v3(160.05,74.34) v3(160.43,74.34) v3(160.82,74.34) v3(161.2,74.34) v3(161.58,74.34) v3(161.96,74.34) v3(162.34,74.34) 162.34,74.53 ; v3(159.29,78.18) v3(159.67,78.18) v3(160.05,78.18) v3(160.43,78.18) v3(160.82,78.18) v3(161.2,78.18) v3(161.58,78.18) v3(161.96,78.18) v3(162.34,78.18) ; v3(168.28,77.33) v3(168.66,77.33) v3(169.04,77.33) v3(169.42,77.33) v3(169.8,77.33) v3(170.18,77.33) v3(170.57,77.33) v3(170.95,77.33) v3(171.33,77.33) ; v3(168.28,75.63) v3(168.66,75.63) v3(169.04,75.63) v3(169.42,75.63) v3(169.8,75.63) v3(170.18,75.63) v3(170.57,75.63) v3(170.95,75.63) v3(171.33,75.63)
  L6_SIG w0.305: 168.24,79.32 v3(168.24,79.56) v3(169.28,79.56) v3(169.69,79.56) v3(170.1,79.56) ; 168.24,79.32 170.07,79.32 ; 168.24,79.32 v3(168.24,79.06) v3(168.75,79.06) v3(169.28,79.06) v3(169.69,79.06) v3(170.1,79.06) ; v3(168.28,75.63) v3(168.66,75.63) v3(169.04,75.63) v3(169.42,75.63) v3(169.8,75.63) v3(170.18,75.63) v3(170.57,75.63) v3(170.95,75.63) v3(171.33,75.63) ; 159.29,74.53 v3(159.29,74.34) v3(159.67,74.34) v3(160.05,74.34) v3(160.43,74.34) v3(160.82,74.34) v3(161.2,74.34) v3(161.58,74.34) v3(161.96,74.34) v3(162.34,74.34) 162.34,74.53 ; 159.29,74.53 162.34,74.53 ; 159.29,74.53 v3(159.29,74.72) v3(159.67,74.72) v3(160.05,74.72) v3(160.43,74.72) v3(160.82,74.72) v3(161.2,74.72) v3(161.58,74.72) v3(161.96,74.72) v3(162.34,74.72) 162.34,74.53 ; v3(171.33,77.33) v3(170.95,77.33) v3(170.57,77.33) v3(170.18,77.33) v3(169.8,77.33) v3(169.42,77.33) v3(169.04,77.33) v3(168.66,77.33) v3(168.28,77.33) ; v3(162.34,78.18) v3(161.96,78.18) v3(161.58,78.18) v3(161.2,78.18) v3(160.82,78.18) v3(160.43,78.18) v3(160.05,78.18) v3(159.67,78.18) v3(159.29,78.18) ; v3(159.29,76.48) v3(159.67,76.48) v3(160.05,76.48) v3(160.43,76.48) v3(160.82,76.48) v3(161.2,76.48) v3(161.58,76.48) v3(161.96,76.48) v3(162.34,76.48)
  L7_SIG w0.305: v3(168.28,77.33) v3(168.66,77.33) v3(169.04,77.33) v3(169.42,77.33) v3(169.8,77.33) v3(170.18,77.33) v3(170.57,77.33) v3(170.95,77.33) v3(171.33,77.33) ; 170.07,79.32 168.25,79.32 168.24,79.31 ; v3(168.28,75.63) v3(168.66,75.63) v3(169.04,75.63) v3(169.42,75.63) v3(169.8,75.63) v3(170.18,75.63) v3(170.57,75.63) v3(170.95,75.63) v3(171.33,75.63) ; 159.29,74.53 v3(159.29,74.72) v3(159.67,74.72) v3(160.05,74.72) v3(160.43,74.72) v3(160.82,74.72) v3(161.2,74.72) v3(161.58,74.72) v3(161.96,74.72) v3(162.34,74.72) 162.34,74.53 ; 159.29,74.53 v3(159.29,74.34) v3(159.67,74.34) v3(160.05,74.34) v3(160.43,74.34) v3(160.82,74.34) v3(161.2,74.34) v3(161.58,74.34) v3(161.96,74.34) v3(162.34,74.34) 162.34,74.53 ; 159.29,74.53 162.34,74.53 ; 168.24,79.31 v3(168.24,79.56) v3(169.28,79.56) v3(169.69,79.56) v3(170.1,79.56) v3(170.1,79.06) v3(169.69,79.06) v3(169.28,79.06) v3(168.75,79.06) v3(168.24,79.06) 168.24,79.31 ; v3(162.34,76.48) v3(161.96,76.48) v3(161.58,76.48) v3(161.2,76.48) v3(160.82,76.48) v3(160.43,76.48) v3(160.05,76.48) v3(159.67,76.48) v3(159.29,76.48) ; v3(162.34,78.18) v3(161.96,78.18) v3(161.58,78.18) v3(161.2,78.18) v3(160.82,78.18) v3(160.43,78.18) v3(160.05,78.18) v3(159.67,78.18) v3(159.29,78.18)
  BOTTOM w0.203: 156.77,65.73 156.54,65.51 R819.1
  BOTTOM w0.254: v2(165.31,67.56) 165.31,66.34 165.08,66.11 157.15,66.11 156.77,65.73
  vias: v2(160.23,69.81) v2(160.23,68.68) v2(160.23,67.56) v2(160.53,65.28) v2(160.54,64.01) v2(160.53,62.74) v2(161.5,69.81) v2(161.5,68.68) v2(161.5,67.56) v2(161.8,65.28) v2(161.81,64.01) v2(161.8,62.74) v2(162.77,69.81) v2(162.77,68.68) v2(162.77,67.56) v2(163.07,65.26) v2(163.07,64.01) v2(163.07,62.74) v2(164.04,69.81) v2(164.04,68.68) v2(164.04,67.56) v2(164.34,65.26) v2(164.34,64.01) v2(164.34,62.74) v2(165.31,69.81) v2(165.31,68.68) v2(165.61,65.28) v2(165.61,64.01) v2(165.61,62.74) v2(166.58,69.81) v2(166.58,68.68) v2(166.58,67.56) v2(166.88,65.28) v2(166.88,64.01) v2(166.88,62.74) v2(167.85,69.81) v2(167.85,68.68) v2(167.85,67.56) v2(168.15,65.28) v2(168.15,64.01) v2(168.15,62.74) v2(169.12,69.81) v2(169.12,68.68) v2(169.12,67.56) v2(169.42,65.28) v2(169.42,64.01) v2(169.42,62.74) v2(170.39,69.81) v2(170.39,68.68) v2(170.39,67.56) v2(170.69,65.28) v2(170.69,64.01) v2(170.69,62.74) v2(171.96,65.28) v2(171.96,64.01) v2(171.96,62.74) v2(173.23,65.28) v2(173.23,64.01) v2(173.23,62.74) v2(174.5,65.28) v2(174.5,64.01) v2(174.5,62.74)
_N220: length 65.5
  L7_SIG w0.305: v2(165.31,56.26) 165.31,55.86 164.81,55.36 155.62,55.36 149.7,49.44 149.7,43.78 146.24,40.32 138.04,40.32 128.79,31.08 121.3,31.08 118.85,28.62 118.85,25.58 119.32,25.1 v3(119.62,25.1)
  vias: v2(160.23,61.2) v2(160.23,60.07) v2(160.23,58.95) v2(161.5,61.2) v2(161.5,60.07) v2(161.5,58.95) v2(162.77,61.2) v2(162.77,60.07) v2(162.77,58.95) v2(164.04,61.2) v2(164.04,60.07) v2(164.04,58.95) v2(165.31,61.2) v2(165.31,60.07) v2(165.31,58.95) v2(166.58,61.2) v2(166.58,60.07) v2(166.58,58.95) v2(167.85,61.2) v2(167.85,60.07) v2(167.85,58.95) v2(169.12,61.2) v2(169.12,60.07) v2(169.12,58.95) v2(170.39,61.2) v2(170.39,60.07) v2(170.39,58.95)
_N221: length 1.8
  TOP w0.203: U6.A4 193.66,83.41 192.85,84.21 R824.2
_N222: length 1.9
  TOP w0.203: U6.B4 194.06,83.83 193.46,84.44 C868.2
_N223: length 2.1
  TOP w0.203: U6.C4 194.46,83.71 195.13,84.38 195.13,84.56 R827.1
_N224: length 1
  TOP w0.203: U6.D3 195.55,82.74 C871.1
_N225: length 1
  TOP w0.203: U6.B1 194.06,81.23 R829.1
_N226: length 0.9
  TOP w0.203: R828.1 195.49,82.34 U6.D2
_N227: length 105.5
  TOP w0.203: U6.C1 194.46,81.26 v3(194.64,81.08) 195.63,80.08 198.71,80.08 198.87,79.92 198.87,79.46 ; U6.D4 194.86,83.48 195.32,83.94 v3(195.75,83.94)
  L2_PWR w0.203: 197.69,80.14 v3(197.69,79.54)
  L2_PWR w0.508: 197.69,80.14 197.69,81.35 v3(197.69,81.35) v3(197.69,81.86)
  L5_GND w0.305: 188.24,74.53 v3(188.24,74.72) v3(188.62,74.72) v3(189,74.72) v3(189.39,74.72) v3(189.77,74.72) v3(190.15,74.72) v3(190.53,74.72) v3(190.91,74.72) v3(191.29,74.72) 191.29,74.53 ; 188.24,74.53 v3(188.24,74.34) v3(188.62,74.34) v3(189,74.34) v3(189.39,74.34) v3(189.77,74.34) v3(190.15,74.34) v3(190.53,74.34) v3(190.91,74.34) v3(191.29,74.34) 191.29,74.53 ; 188.24,74.53 191.29,74.53 ; v3(197.23,77.33) v3(197.61,77.33) v3(197.99,77.33) v3(198.37,77.33) v3(198.75,77.33) v3(199.14,77.33) v3(199.52,77.33) v3(199.9,77.33) v3(200.28,77.33) ; v3(191.29,76.48) v3(190.91,76.48) v3(190.53,76.48) v3(190.15,76.48) v3(189.77,76.48) v3(189.39,76.48) v3(189,76.48) v3(188.62,76.48) v3(188.24,76.48) ; v3(191.29,78.18) v3(190.91,78.18) v3(190.53,78.18) v3(190.15,78.18) v3(189.77,78.18) v3(189.39,78.18) v3(189,78.18) v3(188.62,78.18) v3(188.24,78.18) ; v3(200.28,75.63) v3(199.9,75.63) v3(199.52,75.63) v3(199.14,75.63) v3(198.75,75.63) v3(198.37,75.63) v3(197.99,75.63) v3(197.61,75.63) v3(197.23,75.63) ; 197.17,79.3 199,79.3 ; 197.17,79.3 v3(197.17,79.54) v3(198.22,79.54) v3(198.62,79.54) v3(199.03,79.54) v3(199.03,79.03) ; 197.17,79.3 v3(197.17,79.03) v3(197.68,79.03) v3(198.22,79.03) v3(198.62,79.03)
  L6_SIG w0.305: 188.24,74.53 v3(188.24,74.72) v3(188.62,74.72) v3(189,74.72) v3(189.39,74.72) v3(189.77,74.72) v3(190.15,74.72) v3(190.53,74.72) v3(190.91,74.72) v3(191.29,74.72) 191.29,74.53 ; 188.24,74.53 v3(188.24,74.34) v3(188.62,74.34) v3(189,74.34) v3(189.39,74.34) v3(189.77,74.34) v3(190.15,74.34) v3(190.53,74.34) v3(190.91,74.34) v3(191.29,74.34) 191.29,74.53 ; 188.24,74.53 191.29,74.53 ; v3(199.03,79.03) v3(198.62,79.03) v3(198.22,79.03) v3(197.68,79.03) v3(197.17,79.03) 197.17,79.3 ; 197.17,79.3 v3(197.17,79.54) v3(198.22,79.54) v3(198.62,79.54) v3(199.03,79.54) ; 197.17,79.3 199,79.3 ; v3(191.29,78.18) v3(190.91,78.18) v3(190.53,78.18) v3(190.15,78.18) v3(189.77,78.18) v3(189.39,78.18) v3(189,78.18) v3(188.62,78.18) v3(188.24,78.18) ; v3(200.28,75.63) v3(199.9,75.63) v3(199.52,75.63) v3(199.14,75.63) v3(198.75,75.63) v3(198.37,75.63) v3(197.99,75.63) v3(197.61,75.63) v3(197.23,75.63) ; v3(188.24,76.48) v3(188.62,76.48) v3(189,76.48) v3(189.39,76.48) v3(189.77,76.48) v3(190.15,76.48) v3(190.53,76.48) v3(190.91,76.48) v3(191.29,76.48) ; v3(200.28,77.33) v3(199.9,77.33) v3(199.52,77.33) v3(199.14,77.33) v3(198.75,77.33) v3(198.37,77.33) v3(197.99,77.33) v3(197.61,77.33) v3(197.23,77.33)
  L7_SIG w0.305: 188.24,74.53 v3(188.24,74.34) v3(188.62,74.34) v3(189,74.34) v3(189.39,74.34) v3(189.77,74.34) v3(190.15,74.34) v3(190.53,74.34) v3(190.91,74.34) v3(191.29,74.34) 191.29,74.53 ; 188.24,74.53 v3(188.24,74.72) v3(188.62,74.72) v3(189,74.72) v3(189.39,74.72) v3(189.77,74.72) v3(190.15,74.72) v3(190.53,74.72) v3(190.91,74.72) v3(191.29,74.72) 191.29,74.53 ; 188.24,74.53 191.29,74.53 ; 199,79.3 197.18,79.3 197.17,79.29 ; v3(197.23,75.63) v3(197.61,75.63) v3(197.99,75.63) v3(198.37,75.63) v3(198.75,75.63) v3(199.14,75.63) v3(199.52,75.63) v3(199.9,75.63) v3(200.28,75.63) ; 197.17,79.29 v3(197.17,79.03) v3(197.68,79.03) v3(198.22,79.03) v3(198.62,79.03) v3(199.03,79.03) v3(199.03,79.54) v3(198.62,79.54) v3(198.22,79.54) v3(197.17,79.54) 197.17,79.29 ; v3(188.24,76.48) v3(188.62,76.48) v3(189,76.48) v3(189.39,76.48) v3(189.77,76.48) v3(190.15,76.48) v3(190.53,76.48) v3(190.91,76.48) v3(191.29,76.48) ; v3(200.28,77.33) v3(199.9,77.33) v3(199.52,77.33) v3(199.14,77.33) v3(198.75,77.33) v3(198.37,77.33) v3(197.99,77.33) v3(197.61,77.33) v3(197.23,77.33) ; v3(191.29,78.18) v3(190.91,78.18) v3(190.53,78.18) v3(190.15,78.18) v3(189.77,78.18) v3(189.39,78.18) v3(189,78.18) v3(188.62,78.18) v3(188.24,78.18)
  BOTTOM w0.203: 185.79,65.93 185.78,65.94 R830.1
  BOTTOM w0.254: v2(195.43,67.13) 195.43,66.67 195.21,66.45 186.32,66.45 185.79,65.93
  vias: v2(188.47,65.28) v2(188.46,64.01) v2(188.47,62.74) v2(189.73,64.01) v2(189.74,65.28) v2(189.74,62.74) v2(190.35,69.38) v2(190.35,68.25) v2(190.36,67.37) v2(191.01,65.28) v2(191,64.01) v2(191.01,62.74) v2(191.62,69.38) v2(191.62,68.25) v2(191.63,67.37) v2(192.25,65.26) v2(192.28,64.01) v2(192.28,62.74) v2(192.89,69.38) v2(192.89,68.25) v2(192.9,67.37) v2(193.55,65.28) v2(193.55,64.01) v2(193.55,62.74) v2(194.16,69.38) v2(194.16,68.25) v2(194.17,67.37) v2(194.82,65.28) v2(194.82,64.01) v2(194.82,62.74) v2(195.43,69.38) v2(195.43,68.25) v2(196.09,65.28) v2(196.09,64.01) v2(196.09,62.74) v2(196.7,69.38) v2(196.7,68.25) v2(196.7,67.13) v2(197.36,65.28) v2(197.36,64.01) v2(197.36,62.74) v2(197.97,69.38) v2(197.97,68.25) v2(197.97,67.13) v2(198.63,65.28) v2(198.63,64.01) v2(198.63,62.74) v2(199.24,69.38) v2(199.24,68.25) v2(199.24,67.13) v2(199.9,65.28) v2(199.9,64.01) v2(199.9,62.74) v2(200.51,69.38) v2(200.51,68.25) v2(200.51,67.13) v2(201.17,65.28) v2(201.17,64.01) v2(201.17,62.74) v2(202.44,65.28) v2(202.44,64.01) v2(202.44,62.74)
_N228: length 88.6
  L7_SIG w0.305: v3(121.12,25.1) 121.43,25.1 122.33,24.21 128.09,24.21 137.46,33.58 165.76,33.58 180.64,48.45 180.64,51.17 184.6,55.13 193.53,55.13 194.26,55.86 v2(194.26,56.26)
  vias: v2(190.35,60.77) v2(190.35,59.64) v2(190.35,58.52) v2(191.62,60.77) v2(191.62,59.64) v2(191.62,58.52) v2(192.89,60.77) v2(192.89,59.64) v2(192.89,58.52) v2(194.16,60.77) v2(194.16,59.64) v2(194.16,58.52) v2(195.43,60.77) v2(195.43,59.64) v2(195.43,58.52) v2(196.7,60.77) v2(196.7,59.64) v2(196.7,58.52) v2(197.97,60.77) v2(197.97,59.64) v2(197.97,58.52) v2(199.24,60.77) v2(199.24,59.64) v2(199.24,58.52) v2(200.51,60.77) v2(200.51,59.64) v2(200.51,58.52)
_N265: length 4.1
  BOTTOM w0.381: S1.1 R425.1 217.63,24.94 217.59,24.98 R6.1
_N266: length 4.1
  BOTTOM w0.381: R13.1 217.55,19.88 217.63,19.96 R438.1 S1.3
_N267: length 1.9
  BOTTOM w0.203: R5.2 S1.4
_N375: length 10.4
  TOP w0.203: Q1.1 41.99,79.13 ; U1.D1 36.88,81.51 37.26,81.13 R3.2
  TOP w0.508: 41.03,81.22 41.38,80.86 ; 41.03,81.22 J15.1 ; 41.03,81.22 40.67,80.86 ; 41.38,80.86 42.04,80.2 42.04,79.08 ; 41.38,80.86 40.67,80.86 ; 40.67,80.86 40.44,80.63 38.85,80.63 38.35,81.13 R3.2
_N376: length 9.3
  TOP w0.203: R4.2 34.86,81.13 U1.A1 ; Q2.1 33.05,79.32
  TOP w0.508: P1.1 32.18,80.55 32.63,80.55 ; R4.2 34.86,80.96 34.45,80.55 33.47,80.55 ; 33.05,80.13 33.05,80.55 ; 33.05,80.13 33.47,80.55 ; 33.05,80.13 33.05,79.32 ; 33.05,80.13 32.63,80.55 ; 33.05,80.55 32.63,80.55 ; 33.05,80.55 33.47,80.55
_N377: length 10.4
  TOP w0.203: R715.2 66.21,81.13 65.83,81.51 U2.D1 ; Q3.1 70.94,79.13
  TOP w0.508: 70.33,80.86 69.98,81.22 ; 70.33,80.86 69.62,80.86 ; 70.33,80.86 70.99,80.2 70.99,79.08 ; 69.98,81.22 J17.1 ; 69.98,81.22 69.62,80.86 ; 69.62,80.86 69.39,80.63 67.8,80.63 67.3,81.13 R715.2
_N378: length 8.9
  TOP w0.203: U2.A1 63.81,81.13 R716.2 ; Q4.1 61.96,79.13
  TOP w0.508: 61.58,80.55 62.42,80.55 ; 61.58,80.55 61.19,80.55 P3.1 ; 61.58,80.55 62,80.13 ; 62.42,80.55 63.4,80.55 63.81,80.96 R716.2 ; 62.42,80.55 62,80.13 ; 62,79.32 62,80.13
_N379: length 10.4
  TOP w0.203: R726.2 101.77,81.13 101.39,81.51 U3.D1 ; Q5.1 106.51,79.13
  TOP w0.508: 105.9,80.86 106.56,80.2 106.56,79.08 ; 105.9,80.86 105.54,81.22 ; 105.9,80.86 105.19,80.86 ; R726.2 102.86,81.13 103.36,80.63 104.95,80.63 105.19,80.86 ; 105.54,81.22 J3.1 ; 105.54,81.22 105.19,80.86
_N380: length 8.9
  TOP w0.203: U3.A1 99.38,81.13 R727.2 ; Q6.1 97.52,79.13
  TOP w0.508: 97.57,80.13 97.99,80.55 ; 97.57,80.13 97.57,79.32 ; 97.57,80.13 97.15,80.55 ; 97.99,80.55 97.15,80.55 ; 97.99,80.55 98.96,80.55 99.38,80.96 R727.2 ; 97.15,80.55 96.78,80.55 P5.1
_N381: length 10.4
  TOP w0.203: Q7.1 135.46,79.13 135.51,79.08 ; R805.2 130.72,81.13 130.34,81.51 U4.D1
  TOP w0.508: 134.85,80.86 134.14,80.86 ; 134.85,80.86 135.51,80.2 135.51,79.08 ; 134.85,80.86 134.49,81.22 ; 134.14,80.86 133.9,80.63 132.32,80.63 131.81,81.13 R805.2 ; 134.14,80.86 134.49,81.22 ; 134.49,81.22 J4.1
_N382: length 8.9
  TOP w0.203: U4.A1 128.33,81.13 R806.2 ; Q8.1 126.47,79.13
  TOP w0.508: 126.52,79.32 126.52,80.13 ; 126.52,80.13 126.1,80.55 ; 126.52,80.13 126.94,80.55 ; 126.1,80.55 125.67,80.55 P7.1 ; 126.1,80.55 126.94,80.55 ; 126.94,80.55 127.91,80.55 128.33,80.96 R806.2
_N383: length 10.4
  TOP w0.203: U5.D1 165.91,81.51 166.29,81.13 R817.2 ; 171.07,79.08 171.03,79.13 Q9.1
  TOP w0.508: 170.41,80.86 171.07,80.2 171.07,79.08 ; 170.41,80.86 169.7,80.86 ; 170.41,80.86 170.06,81.22 ; 169.7,80.86 170.06,81.22 ; 169.7,80.86 169.47,80.63 167.88,80.63 167.38,81.13 R817.2 ; 170.06,81.22 J16.1
_N384: length 8.8
  TOP w0.203: U5.A1 163.89,81.13 R818.2 ; Q10.1 162.08,79.32
  TOP w0.508: 162.5,80.55 163.48,80.55 163.89,80.96 R818.2 ; 162.5,80.55 161.66,80.55 ; 162.5,80.55 162.08,80.13 ; 161.66,80.55 161.27,80.55 P9.1 ; 161.66,80.55 162.08,80.13 ; 162.08,80.13 162.08,79.32
_N385: length 10.4
  TOP w0.203: Q11.1 199.98,79.13 200.02,79.08 ; U6.D1 194.86,81.51 195.24,81.13 R828.2
  TOP w0.508: 199.36,80.86 200.02,80.2 200.02,79.08 ; 199.36,80.86 198.65,80.86 ; 199.36,80.86 199.01,81.22 ; 198.65,80.86 198.42,80.63 196.83,80.63 196.33,81.13 R828.2 ; 198.65,80.86 199.01,81.22 ; 199.01,81.22 J14.1
_N386: length 8.8
  TOP w0.203: Q12.1 191.03,79.32 ; U6.A1 192.84,81.13 R829.2
  TOP w0.508: 191.45,80.55 190.62,80.55 ; 191.45,80.55 192.43,80.55 192.84,80.96 R829.2 ; 191.45,80.55 191.03,80.13 ; 190.62,80.55 191.03,80.13 ; 190.62,80.55 190.19,80.55 P11.1 ; 191.03,79.32 191.03,80.13
_N505: length 4.6
  BOTTOM w0.203: P28.4 R465.2 R466.1 C194.1
BUCK: length 143.1
  TOP w0.203: v3(113.06,31.54) 113.06,32.58 U7.54
  L6_SIG w0.203: E4.1 214.6,39.71 201.74,39.71 200.89,38.86 122.74,38.86 122.27,38.39 121.89,38.39 121.74,38.54 120.56,38.54 113.55,31.54 v3(113.06,31.54)
  L7_SIG w0.203: E4.1 225.31,43.54 225.31,24.23 S1.5
CSB: length 174
  TOP w0.203: U7.37 107.41,40.09 106.43,39.1 v3(106.43,38.85)
  L6_SIG w0.203: E31.1 2.73,65.85 2.73,18.08 3.99,16.83 v1(3.99,14.28)
  L7_SIG w0.203: v1(3.99,14.28) 6.66,16.96 18.85,16.96 20.34,18.45 27.25,18.45 33.74,24.94 65.36,24.94 75.76,35.33 101.89,35.33 105.42,38.85 v3(106.43,38.85)
  BOTTOM w0.203: R416.2 v1(3.99,14.28)
DRVCC: length 75.5
  TOP w0.203: U4.A3 128.74,82.74 128.34,83.15 C802.1 ; U1.A3 35.28,82.74 34.87,83.15 C1.1 ; U3.A3 99.79,82.74 99.38,83.15 C752.1 ; U5.A3 164.31,82.74 163.9,83.15 C836.1 ; U6.A3 193.26,82.74 192.85,83.15 C870.1 ; U2.A3 64.23,82.74 63.82,83.15 C718.1
  TOP w0.254: C31.1 106.23,34.1 v1(106.64,34.52) 107.72,35.59 U7.46
  L6_SIG w0.508: v1(106.64,34.52) 108.24,36.11 108.24,40.06 107.53,40.77 107.53,44.15 109.27,45.9 109.27,52.46 111.31,54.49 111.31,56.29 112.46,57.44 112.46,79.92 111.95,80.43 98.29,80.43 97.25,81.47 v3(97.25,83.12)
  vias: v3(32.73,83.12) v3(61.69,83.12) v3(126.2,83.12) v3(161.77,83.12) v3(190.72,83.12)
PGOOD: length 140.5
  TOP w0.203: v3(107.38,46.94) R123.2 108.14,46.44 109.55,45.03 111.35,45.03 111.55,44.83 U7.30
  L6_SIG w0.203: E33.1 21.59,77.84 21.59,66.59 23.58,64.6 75.64,64.6 81.12,59.12 81.12,47.96 84.23,44.84 105.29,44.84 v3(107.38,46.94)
PWM1: length 122
  TOP w0.203: U7.29 112.05,44.87 111.43,45.49 v3(110.55,45.49)
  L6_SIG w0.203: v3(110.55,45.49) 110.37,45.67 110.37,48.74 112.34,50.71 112.34,55.51 113.45,56.63 113.45,81.57 112.39,82.62 100.21,82.62 97.34,85.49 94.25,85.49 90.88,82.12 72.55,82.12 69.31,85.37 63.89,85.37 62.81,86.44 37.04,86.44 v3(36.43,85.83)
PWM2: length 95.3
  TOP w0.203: v3(110.07,43.16) 110.87,43.16 111.05,43.34 U7.31
  L6_SIG w0.203: v3(110.07,43.16) 109.61,43.62 109.61,44.54 109.81,44.75 110.47,44.75 111.05,45.33 111.05,47.21 113.28,49.44 113.28,54.93 114.28,55.93 114.28,82.09 112.9,83.47 101.27,83.47 99.97,84.77 99.97,86.15 99.36,86.76 66.31,86.76 v3(65.38,85.83)
PWM3: length 58
  TOP w0.203: U7.32 v3(110.07,44.09)
  L6_SIG w0.203: v3(110.07,44.09) 111.21,44.09 111.97,44.85 111.97,46.73 115.19,49.96 115.19,83.41 113.62,84.98 104.81,84.98 104.62,84.79 102.75,84.79 102.56,84.98 101.8,84.98 v3(100.94,85.83)
PWM4: length 63.1
  TOP w0.203: U7.33 v3(108.55,42.57)
  L6_SIG w0.203: v3(129.89,85.83) 129.56,85.5 123.42,85.5 120.14,82.21 120.14,54.83 121.56,53.41 121.56,47.76 115.19,41.39 109.35,41.39 108.55,42.19 v3(108.55,42.57)
PWM5: length 100.6
  TOP w0.203: U7.34 109.31,41.59 109.48,41.76 v3(109.48,42.57)
  L6_SIG w0.203: v3(109.48,42.57) 109.48,42.36 109.87,41.96 114.25,41.96 120.29,48 120.29,49.08 119.79,49.57 119.79,50.42 120.29,50.92 120.29,53.36 118.97,54.67 118.97,82.23 124.42,87.67 140.11,87.67 141.47,86.31 150.28,86.31 150.72,86.76 164.53,86.76 v3(165.46,85.83)
PWM6: length 130.5
  TOP w0.203: U7.36 109.3,40.59 109.99,41.28 v3(109.99,42.57)
  L6_SIG w0.203: v3(109.99,42.57) 113.21,42.57 118.7,48.07 118.7,53.48 118.02,54.17 118.02,83.82 122.81,88.61 140.6,88.61 142.13,87.07 149.59,87.07 150.67,88.16 175.83,88.16 177.53,86.45 193.79,86.45 v3(194.41,85.83)
PWMEN: length 97.1
  TOP w0.203: R418.2 109.39,46.44 109.88,45.95 110.74,45.95 110.8,45.88 111.58,45.88 112.18,45.27 v3(112.55,45.27) U7.28
  L6_SIG w0.203: v3(112.55,45.27) 116.12,48.84 116.12,83.94 114.23,85.83 v3(102.92,85.83)
  L7_SIG w0.203: v3(38.41,85.83) 37.71,85.83 35.34,88.2 18.86,88.2 E22.1
  vias: v3(67.36,85.83) v3(131.88,85.83) v3(167.44,85.83) v3(196.39,85.83)
RUN: length 199.6
  TOP w0.203: v3(113.09,45.15) 113.09,44.89 113.05,44.85 U7.27
  L6_SIG w0.203: v3(113.09,45.15) 113.4,45.15 117,48.75 117,85.02 128.79,96.81 143.78,96.81 144.4,97.44 149.71,97.44 150.33,96.81 175.29,96.81 176.15,97.67 183.58,97.67 184.43,96.81 204.36,96.81 211.74,104.19 E34.1 224.2,101.86 224.2,79.12 P28.2
  BOTTOM w0.203: P28.2 P28.3 222.97,73.69 222.97,65.32 JP4.2
SAC1: length 127.3
  TOP w0.203: 120.83,49.85 120.83,49.86 v3(120.83,49.88) ; C715.1 122.62,47.01 119.7,44.09 U7.17
  L7_SIG w0.508: v3(120.83,49.88) 121.11,49.59 121.11,46.37 115.78,41.04 115.78,40.33 115.28,39.82 107.48,39.82 107.13,40.18 104,40.18 103.02,39.2 101,39.2 100.53,39.66 88,39.66 86.83,38.49 71.45,38.49 70.34,39.61 53.69,39.61 51.29,37.21 48.78,37.21 47.63,38.35 41.04,38.35 38.91,40.48 38.91,46.15 27.43,57.63 v1(27.43,61.08)
  BOTTOM w0.508: R706.2 27.43,61.59 27.43,61.58 v1(27.43,61.08)
